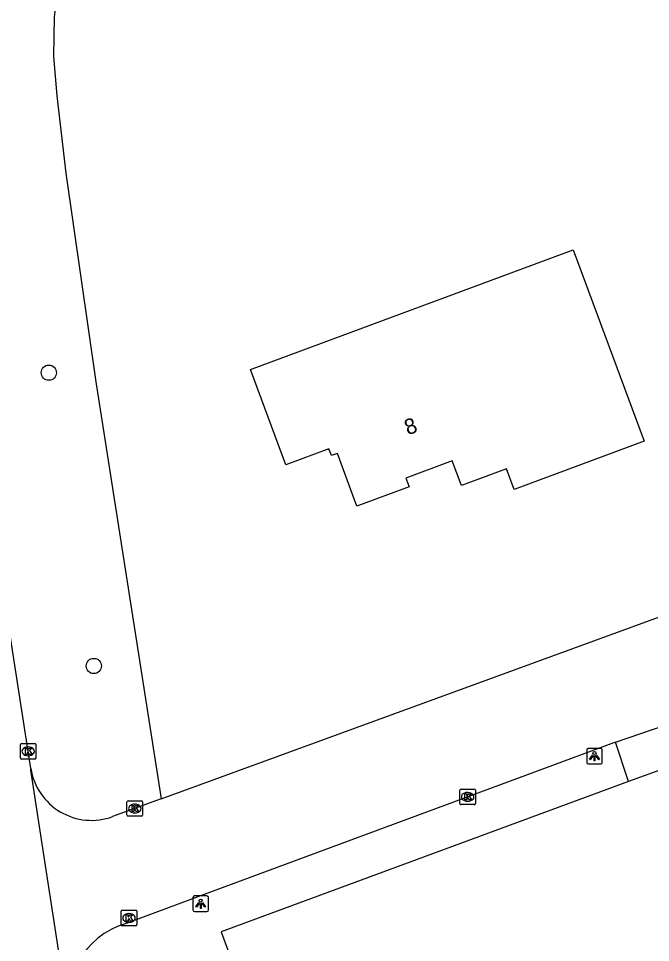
# Model space of a CAD drawing. Extents: x 162417 to 163721, y 384268 to 385416.
# Drawn here: x 163278.1 to 163318.6, y 385131.8 to 385191.1 of the extents above; entities that cross this region are included whole.
import ezdxf

# ---------------------------------------------------------------- set-up
doc = ezdxf.new("R2010")
doc.units = 0
for name, color, linetype in [('IMGEO_Boom', 7, 'Continuous'), ('IMGEO_Groenvoorziening', 7, 'Continuous'), ('IMGEO_Kolk', 7, 'Continuous'), ('IMGEO_Lichtpunt', 7, 'Continuous'), ('IMGEO_Pand', 7, 'Continuous'), ('IMGEO_Pand_nummerreeks', 7, 'Continuous'), ('IMGEO_Rijbaan_lokaal_gesloten', 7, 'Continuous'), ('IMGEO_Voetpad_open', 7, 'Continuous')]:
    doc.layers.add(name, color=color, linetype=linetype)

msp = doc.modelspace()

# ---------------------------------------------------------------- linework, layer by layer
at = {"layer": 'IMGEO_Boom'}
for centre in [(163280.015, 385168.348), (163282.9, 385149.537)]:
    msp.add_circle(centre, 0.489, dxfattribs=at)
at = {"layer": 'IMGEO_Groenvoorziening'}
for points in [[(163291.283, 385223.567), (163282.7, 385200.315), (163281.529, 385196.973), (163280.579, 385193.07), (163280.36, 385191.142), (163280.307, 385188.617), (163280.519, 385186.099), (163281.095, 385181.154), (163283.03, 385167.757), (163287.208, 385141.009)], [(163317.169, 385142.12), (163291.053, 385132.483), (163297.621, 385114.497)]]:
    msp.add_lwpolyline(points, dxfattribs=at)
at = {"layer": 'IMGEO_Kolk'}
for p, q in [((163278.192, 385143.639), (163278.192, 385144.491)), ((163278.267, 385144.565), (163279.119, 385144.565)), ((163278.68, 385144.345), (163278.705, 385144.345)), ((163279.193, 385144.491), (163279.193, 385143.639)), ((163278.703, 385143.785), (163278.678, 385143.785)), ((163279.119, 385143.565), (163278.267, 385143.565)), ((163306.356, 385140.717), (163306.356, 385141.569)), ((163306.431, 385141.643), (163307.283, 385141.643)), ((163306.844, 385141.423), (163306.869, 385141.423)), ((163307.357, 385141.569), (163307.357, 385140.717)), ((163285.025, 385139.969), (163285.025, 385140.821)), ((163285.1, 385140.895), (163285.952, 385140.895)), ((163286.026, 385140.821), (163286.026, 385139.969)), ((163306.867, 385140.863), (163306.842, 385140.863)), ((163285.513, 385140.675), (163285.538, 385140.675)), ((163307.283, 385140.643), (163306.431, 385140.643)), ((163285.952, 385139.895), (163285.1, 385139.895)), ((163285.536, 385140.115), (163285.511, 385140.115)), ((163284.652, 385132.954), (163284.652, 385133.806)), ((163284.727, 385133.88), (163285.579, 385133.88)), ((163285.14, 385133.66), (163285.165, 385133.66)), ((163285.653, 385133.806), (163285.653, 385132.954)), ((163285.163, 385133.1), (163285.138, 385133.1)), ((163285.579, 385132.88), (163284.727, 385132.88))]:
    msp.add_line(p, q, dxfattribs=at)
for points in [[(163278.192, 385143.639), (163278.192, 385144.491)], [(163278.267, 385144.565), (163279.119, 385144.565)], [(163279.193, 385144.491), (163279.193, 385143.639)], [(163278.513, 385144.265), (163278.636, 385144.265), (163278.636, 385144.114), (163278.766, 385144.265), (163278.93, 385144.265), (163278.784, 385144.114), (163278.937, 385143.865), (163278.785, 385143.865), (163278.7, 385144.029), (163278.636, 385143.962), (163278.636, 385143.865), (163278.513, 385143.865), (163278.513, 385144.265)], [(163279.119, 385143.565), (163278.267, 385143.565)], [(163306.356, 385140.717), (163306.356, 385141.569)], [(163306.431, 385141.643), (163307.283, 385141.643)], [(163306.677, 385141.343), (163306.8, 385141.343), (163306.8, 385141.192), (163306.93, 385141.343), (163307.094, 385141.343), (163306.948, 385141.192), (163307.101, 385140.943), (163306.949, 385140.943), (163306.864, 385141.107), (163306.8, 385141.04), (163306.8, 385140.943), (163306.677, 385140.943), (163306.677, 385141.343)], [(163307.357, 385141.569), (163307.357, 385140.717)], [(163285.025, 385139.969), (163285.025, 385140.821)], [(163285.1, 385140.895), (163285.952, 385140.895)], [(163286.026, 385140.821), (163286.026, 385139.969)], [(163285.346, 385140.595), (163285.469, 385140.595), (163285.469, 385140.444), (163285.599, 385140.595), (163285.763, 385140.595), (163285.617, 385140.444), (163285.77, 385140.195), (163285.618, 385140.195), (163285.533, 385140.359), (163285.469, 385140.292), (163285.469, 385140.195), (163285.346, 385140.195), (163285.346, 385140.595)], [(163307.283, 385140.643), (163306.431, 385140.643)], [(163285.952, 385139.895), (163285.1, 385139.895)], [(163284.652, 385132.954), (163284.652, 385133.806)], [(163284.727, 385133.88), (163285.579, 385133.88)], [(163285.653, 385133.806), (163285.653, 385132.954)], [(163284.973, 385133.58), (163285.096, 385133.58), (163285.096, 385133.429), (163285.226, 385133.58), (163285.39, 385133.58), (163285.244, 385133.429), (163285.397, 385133.18), (163285.245, 385133.18), (163285.16, 385133.344), (163285.096, 385133.277), (163285.096, 385133.18), (163284.973, 385133.18), (163284.973, 385133.58)], [(163285.579, 385132.88), (163284.727, 385132.88)]]:
    msp.add_lwpolyline(points, dxfattribs=at)
for centre, start, end in [((163278.269, 385144.489), 91.55205, 178.44795), ((163278.269, 385144.489), 91.55205, 178.44795), ((163279.117, 385144.489), 1.55205, 88.44795), ((163279.117, 385144.489), 1.55205, 88.44795), ((163278.269, 385143.641), 181.55205, 268.44795), ((163278.269, 385143.641), 181.55205, 268.44795), ((163279.117, 385143.641), 271.55205, 358.44795), ((163279.117, 385143.641), 271.55205, 358.44795), ((163306.433, 385141.567), 91.55205, 178.44795), ((163306.433, 385141.567), 91.55205, 178.44795), ((163307.281, 385141.567), 1.55205, 88.44795), ((163307.281, 385141.567), 1.55205, 88.44795), ((163285.102, 385140.819), 91.55205, 178.44795), ((163285.102, 385140.819), 91.55205, 178.44795), ((163285.95, 385140.819), 1.55205, 88.44795), ((163285.95, 385140.819), 1.55205, 88.44795), ((163306.433, 385140.719), 181.55205, 268.44795), ((163306.433, 385140.719), 181.55205, 268.44795), ((163307.281, 385140.719), 271.55205, 358.44795), ((163307.281, 385140.719), 271.55205, 358.44795), ((163285.102, 385139.971), 181.55205, 268.44795), ((163285.102, 385139.971), 181.55205, 268.44795), ((163285.95, 385139.971), 271.55205, 358.44795), ((163285.95, 385139.971), 271.55205, 358.44795), ((163284.729, 385133.804), 91.55205, 178.44795), ((163284.729, 385133.804), 91.55205, 178.44795), ((163285.577, 385133.804), 1.55205, 88.44795), ((163285.577, 385133.804), 1.55205, 88.44795), ((163284.729, 385132.956), 181.55205, 268.44795), ((163284.729, 385132.956), 181.55205, 268.44795), ((163285.577, 385132.956), 271.55205, 358.44795), ((163285.577, 385132.956), 271.55205, 358.44795)]:
    msp.add_arc(centre, 0.0765, start, end, dxfattribs=at)
for centre, major_axis, ratio, start_param, end_param in [((163278.679, 385144.065), (-0.387, 0.002), 0.722429, 4.712389, 7.853982), ((163278.704, 385144.065), (-0.39, 0.002), 0.717154, 1.570796, 4.712389), ((163306.843, 385141.143), (-0.387, 0.002), 0.722429, 4.712389, 7.853982), ((163306.868, 385141.143), (-0.39, 0.002), 0.717154, 1.570796, 4.712389), ((163285.512, 385140.395), (-0.387, 0.002), 0.722429, 4.712389, 7.853982), ((163285.537, 385140.395), (-0.39, 0.002), 0.717154, 1.570796, 4.712389), ((163285.139, 385133.38), (-0.387, 0.002), 0.722429, 4.712389, 7.853982), ((163285.164, 385133.38), (-0.39, 0.002), 0.717154, 1.570796, 4.712389)]:
    msp.add_ellipse(centre, major_axis=major_axis, ratio=ratio, start_param=start_param, end_param=end_param, dxfattribs=at)
at = {"layer": 'IMGEO_Lichtpunt'}
for p, q in [((163314.487, 385144.154), (163314.487, 385143.347)), ((163314.487, 385144.154), (163314.487, 385143.347)), ((163315.389, 385144.249), (163314.581, 385144.249)), ((163315.389, 385144.249), (163314.581, 385144.249)), ((163315.483, 385143.347), (163315.483, 385144.154)), ((163315.483, 385143.347), (163315.483, 385144.154)), ((163314.581, 385143.253), (163315.389, 385143.253)), ((163314.581, 385143.253), (163315.389, 385143.253)), ((163290.151, 385134.79), (163289.343, 385134.79)), ((163290.151, 385134.79), (163289.343, 385134.79)), ((163289.249, 385134.695), (163289.249, 385133.888)), ((163289.249, 385134.695), (163289.249, 385133.888)), ((163290.245, 385133.888), (163290.245, 385134.695)), ((163290.245, 385133.888), (163290.245, 385134.695)), ((163289.343, 385133.794), (163290.151, 385133.794)), ((163289.343, 385133.794), (163290.151, 385133.794))]:
    msp.add_line(p, q, dxfattribs=at)
for points in [[(163314.861, 385143.818), (163314.9, 385143.79), (163314.712, 385143.528), (163314.674, 385143.555), (163314.861, 385143.818)], [(163314.963, 385143.77), (163315.01, 385143.77), (163315.01, 385143.448), (163314.963, 385143.448), (163314.963, 385143.77)], [(163315.073, 385143.79), (163315.111, 385143.817), (163315.298, 385143.555), (163315.259, 385143.527), (163315.073, 385143.79)], [(163289.623, 385134.359), (163289.662, 385134.331), (163289.474, 385134.069), (163289.436, 385134.096), (163289.623, 385134.359)], [(163289.725, 385134.311), (163289.772, 385134.311), (163289.772, 385133.989), (163289.725, 385133.989), (163289.725, 385134.311)], [(163289.835, 385134.331), (163289.873, 385134.358), (163290.06, 385134.096), (163290.021, 385134.068), (163289.835, 385134.331)]]:
    msp.add_lwpolyline(points, dxfattribs=at)
for centre in [(163314.986, 385143.952), (163289.748, 385134.493)]:
    msp.add_circle(centre, 0.0994, dxfattribs=at)
for centre, start, end in [((163314.581, 385144.154), 90, 180), ((163314.581, 385144.154), 90, 180), ((163315.389, 385144.154), 0, 90), ((163315.389, 385144.154), 0, 90), ((163314.581, 385143.347), 180, 270), ((163314.581, 385143.347), 180, 270), ((163315.389, 385143.347), 270, 0), ((163315.389, 385143.347), 270, 360), ((163289.343, 385134.695), 90, 180), ((163289.343, 385134.695), 90, 180), ((163290.151, 385134.695), 0, 90), ((163290.151, 385134.695), 0, 90), ((163289.343, 385133.888), 180, 270), ((163289.343, 385133.888), 180, 270), ((163290.151, 385133.888), 270, 0), ((163290.151, 385133.888), 270, 360)]:
    msp.add_arc(centre, 0.0946, start, end, dxfattribs=at)
at = {"layer": 'IMGEO_Pand'}
msp.add_lwpolyline([(163318.178, 385163.963), (163309.835, 385160.865), (163309.348, 385162.178), (163306.459, 385161.105), (163305.87, 385162.689), (163302.896, 385161.586), (163303.102, 385161.032), (163299.757, 385159.791), (163298.505, 385163.167), (163298.131, 385163.028), (163297.967, 385163.468), (163295.202, 385162.443), (163292.936, 385168.554), (163313.626, 385176.224), (163318.178, 385163.963)], dxfattribs=at)
at = {"layer": 'IMGEO_Rijbaan_lokaal_gesloten'}
for points in [[(163287.208, 385141.009), (163366.356, 385169.942)], [(163278.864, 385142.966), (163276.433, 385158.553)], [(163316.324, 385144.642), (163322.014, 385146.595)], [(163316.324, 385144.642), (163290.133, 385134.945), (163284.964, 385133.031)], [(163281.479, 385126.648), (163281.318, 385126.885), (163278.87, 385142.855), (163278.864, 385142.966)], [(163287.208, 385141.009), (163284.103, 385139.877)]]:
    msp.add_lwpolyline(points, dxfattribs=at)
for centre, radius, start, end in [((163282.75, 385143.57), 3.933, 188.83552, 290.11588), ((163286.421, 385128.092), 5.149, 106.44077, 196.29178)]:
    msp.add_arc(centre, radius, start, end, dxfattribs=at)
at = {"layer": 'IMGEO_Voetpad_open'}
for points in [[(163317.169, 385142.12), (163316.324, 385144.642)], [(163322.944, 385144.218), (163317.169, 385142.12)]]:
    msp.add_lwpolyline(points, dxfattribs=at)

# ---------------------------------------------------------------- texts
at = {"layer": 'IMGEO_Pand_nummerreeks'}
msp.add_text('8', height=1, rotation=20.34886, dxfattribs=at).set_placement((163303.025, 385164.321))

doc.saveas('drawing.dxf')
